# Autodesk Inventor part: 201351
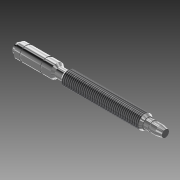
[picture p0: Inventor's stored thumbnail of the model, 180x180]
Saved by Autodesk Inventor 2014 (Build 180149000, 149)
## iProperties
Created: 2007-11
Part Number: 201351
Material: Stainless Steel
Document SubType Name: Modeling
Designer: JJ
Density: 8.08 g/cm^3
Mass: 101.36 g
Surface Area: 47.5454 cm^2
Volume: 12.5446 cm^3
Description: BALL SCREW SHAFT
Appearance: Chrome - Polished
CustomPartVersion: 1
Component Category: Lower Component
Author: JJ
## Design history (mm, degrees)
sketch "Main Sketch"
  geometry: L1 (0, 0)-(127.25, 0) reference; L2 (0, 0)-(0, 4); L3 (0, 4)-(3, 4); L4 (3, 4)-(3, 6); L5 (36.25, 6)-(36.25, 4); L6 (3, 6)-(36.25, 6); L7 (36.25, 4)-(42.25, 4); L8 (42.25, 4)-(42.25, 6); L9 (112.25, 6)-(112.25, 4); L10 (42.25, 6)-(112.25, 6); L11 (127.25, 4)-(127.25, 0); L12 (112.25, 4)-(127.25, 4)
  constraints: 24 end point, 6 vertical, 2 horizontal
  dimensions: "d3" = 8 diameter of L3 L1 (derived); "d4" = 12 diameter of L6 L1 (derived); "d5" = 8 diameter of L7 L1 (derived); "d6" = 12 diameter of L10 L1 (derived); "d17" = 8 diameter of L12 L1 (derived)
revolve "Revolution1" sketch "Main Sketch" stored, may be unused: angle "d7" = 0 deg
feature "iFeature27:3"
feature "iFeature27:2"
feature "iFeature1:1"
chamfer "Chamfer4" distance "d18" = 4.66; stored, may be unused: second distance "d19" = 0.93, angle "d20" = 45 deg
chamfer "Chamfer1" distance "d8" = 2; stored, may be unused: second distance "d9" = 0.125, angle "d10" = 45 deg
chamfer "Chamfer2" distance "d11" = 2; stored, may be unused: second distance "d12" = 0.125, angle "d13" = 45 deg
chamfer "Chamfer3" distance "d14" = 2.25; stored, may be unused: second distance "d15" = 0.125, angle "d16" = 30 deg
sketch "Sketch3"
  geometry: L1 (0, 0)-(0, -6); L2 (2.5, -5.454)-(-2.5, -5.454); A1 r 6 centre (0, 0) between (-2.5, -5.454) and (2.5, -5.454)
  constraints: 4 end point, 3 point on circle, 1 centre point, 1 perpendicular, 1 vertical
  dimensions: "d21" = 5 distance of L2.start L2.end
extrude "Extrusion1" cut sketch "Sketch3" stored distance "d22" = 10; taper "d23" = 0 deg
sketch "Sketch4"
  geometry: L1 (0, 0)-(0, 4); L2 (0, 0)-(0, -4); L3 (0, 2)-(0, -2); A1 r 4 centre (0, 0) between (0, 4) and (0, -4) reference; A2 r 2 centre (0, 0) between (0, -2) and (0, 2)
  constraints: 6 end point, 4 point on circle, 2 collinear, 2 midpoint, 1 centre point, 1 coincident, 1 vertical
  dimensions: "d24" = 2 radius of A2
revolve "Revolution2" sketch "Sketch4" stored, may be unused: angle "d25" = 90 deg
thread "Thread1" dims "d26" = 10, "d27" = 0
body "Solid1"
other parameters: "d0" = 0, "d1" = 0, "d2" = 0
